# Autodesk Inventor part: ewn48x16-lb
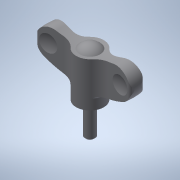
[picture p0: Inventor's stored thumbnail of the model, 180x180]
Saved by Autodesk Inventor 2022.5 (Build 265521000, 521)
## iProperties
Created: 2016-12
Part Number: ewn48x16-lb
Material: 一般
Document SubType Name: Modeling
Designer: imaocorp
Density: 1 g/cm^3
Appearance: 既定
Author: imaocorp
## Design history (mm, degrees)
node "ewn48x16-lb.x_t1"
node "ewn48x16-lb"
node "Base1"
